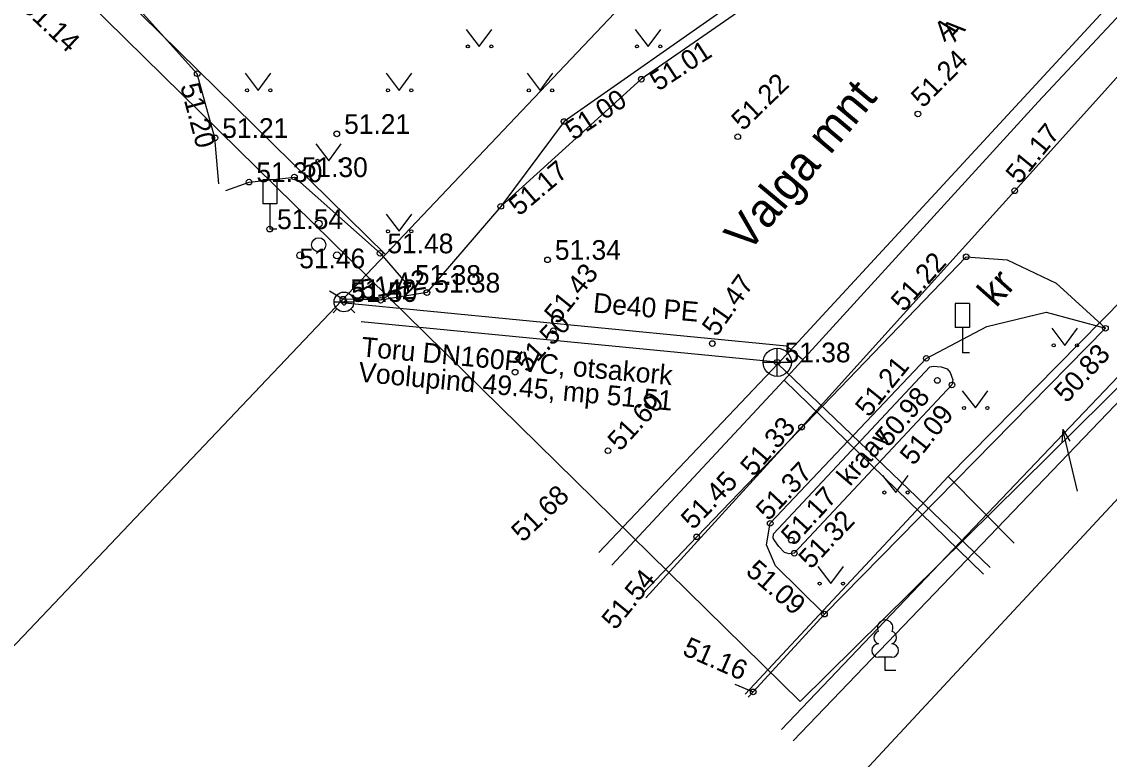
# Model space of a CAD drawing. Extents: x 640876 to 641418, y 6455595 to 6456085.
# Drawn here: x 641203.77 to 641242.36, y 6455734.7 to 6455760.88 of the extents above; entities that cross this region are included whole.
import ezdxf

# ---------------------------------------------------------------- set-up
doc = ezdxf.new("R2010")
doc.units = 0
for name, color, linetype in [('HALJASTUS', 7, 'Continuous'), ('KKAEV', 7, 'Continuous'), ('KORGUS', 7, 'Continuous'), ('KTRASS', 7, 'Continuous'), ('LIIKLUS', 7, 'Continuous'), ('MOOTKORG', 7, 'Continuous'), ('MOOTMPUNKT', 7, 'Continuous'), ('MOOTPIIR', 7, 'Continuous'), ('MPOHULIIN', 7, 'Continuous'), ('PIIR', 7, 'Continuous'), ('PUU', 7, 'Continuous'), ('SITRASS', 7, 'Continuous'), ('TEE', 7, 'Continuous'), ('VEEKOGU', 7, 'Continuous'), ('VKAEV', 7, 'Continuous'), ('VTRASS', 7, 'Continuous')]:
    doc.layers.add(name, color=color, linetype=linetype)

msp = doc.modelspace()

# ---------------------------------------------------------------- linework, layer by layer
at = {"layer": 'HALJASTUS'}
for p, q in [((641219.537, 6455760.607), (641220, 6455760)), ((641220, 6455760), (641220.446, 6455760.607)), ((641225.537, 6455760.607), (641226, 6455760)), ((641226, 6455760), (641226.446, 6455760.607)), ((641211.699, 6455759.047), (641212.162, 6455758.44)), ((641212.162, 6455758.44), (641212.608, 6455759.047)), ((641216.699, 6455759.047), (641217.162, 6455758.44)), ((641217.162, 6455758.44), (641217.608, 6455759.047)), ((641221.699, 6455759.047), (641222.162, 6455758.44)), ((641222.162, 6455758.44), (641222.608, 6455759.047)), ((641214.199, 6455756.547), (641214.662, 6455755.94)), ((641214.662, 6455755.94), (641215.108, 6455756.547)), ((641216.699, 6455754.047), (641217.162, 6455753.44)), ((641217.162, 6455753.44), (641217.608, 6455754.047)), ((641240.324, 6455749.995), (641240.787, 6455749.389)), ((641240.787, 6455749.389), (641241.233, 6455749.995)), ((641237.144, 6455747.774), (641237.607, 6455747.167)), ((641237.607, 6455747.167), (641238.053, 6455747.774)), ((641234.316, 6455744.77), (641234.78, 6455744.164)), ((641234.78, 6455744.164), (641235.225, 6455744.77)), ((641232.019, 6455741.539), (641232.483, 6455740.933)), ((641232.483, 6455740.933), (641232.928, 6455741.539))]:
    msp.add_line(p, q, dxfattribs=at)
msp.add_lwpolyline([(641211.007, 6455754.889), (641211.832, 6455755.185), (641213.444, 6455755.363), (641216.482, 6455752.657), (641217.46, 6455751.537), (641216.502, 6455750.988)], dxfattribs=at)
for centre in [(641219.599, 6455760), (641220.428, 6455760), (641225.599, 6455760), (641226.428, 6455760), (641211.761, 6455758.44), (641212.59, 6455758.44), (641216.761, 6455758.44), (641217.59, 6455758.44), (641221.761, 6455758.44), (641222.59, 6455758.44), (641214.261, 6455755.94), (641215.09, 6455755.94), (641216.761, 6455753.44), (641217.59, 6455753.44), (641240.386, 6455749.389), (641241.215, 6455749.389), (641237.206, 6455747.167), (641238.035, 6455747.167), (641234.379, 6455744.164), (641235.208, 6455744.164), (641232.082, 6455740.933), (641232.911, 6455740.933)]:
    msp.add_circle(centre, 0.055, dxfattribs=at)
at = {"layer": 'KKAEV'}
for p, q in [((641230.577, 6455748.287), (641230.577, 6455749.287)), ((641230.077, 6455748.787), (641231.077, 6455748.787))]:
    msp.add_line(p, q, dxfattribs=at)
msp.add_circle((641230.577, 6455748.787), 0.5, dxfattribs=at)
at = {"layer": 'KORGUS'}
for centre in [(641209.995, 6455759.033), (641225.754, 6455758.837), (641223.014, 6455757.336), (641235.569, 6455757.604), (641214.947, 6455756.896), (641229.176, 6455756.796), (641239.003, 6455754.877), (641220.766, 6455754.323), (641216.482, 6455752.657), (641237.282, 6455752.533), (641216.502, 6455750.988), (641242.224, 6455749.994), (641222.63, 6455749.907), (641228.271, 6455749.453), (641235.865, 6455748.928), (641221.275, 6455748.434), (641236.26, 6455748.144), (641236.777, 6455747.982), (641231.439, 6455746.488), (641224.569, 6455745.648), (641230.327, 6455743.071), (641227.72, 6455742.592), (641231.078, 6455742.473), (641231.181, 6455742.011), (641232.253, 6455739.847), (641229.724, 6455737.087)]:
    msp.add_circle(centre, 0.1, dxfattribs=at)
at = {"layer": 'KTRASS'}
msp.add_line((641230.577, 6455748.787), (641215.813, 6455750.225), dxfattribs=at)
for points in [[(641230.602, 6455748.736), (641246.182, 6455765.632)], [(641224.25, 6455742.039), (641230.602, 6455748.736), (641238.136, 6455741.504)]]:
    msp.add_lwpolyline(points, dxfattribs=at)
at = {"layer": 'LIIKLUS'}
for p, q in [((641212.318, 6455755.267), (641212.318, 6455754.417)), ((641212.818, 6455755.267), (641212.318, 6455755.267)), ((641212.818, 6455755.267), (641212.818, 6455754.417)), ((641212.818, 6455754.417), (641212.318, 6455754.417)), ((641212.568, 6455754.417), (641212.568, 6455753.517)), ((641212.818, 6455753.517), (641212.568, 6455753.517)), ((641236.896, 6455750.876), (641236.896, 6455750.026)), ((641237.396, 6455750.876), (641236.896, 6455750.876)), ((641237.396, 6455750.876), (641237.396, 6455750.026)), ((641237.396, 6455750.026), (641236.896, 6455750.026)), ((641237.146, 6455750.026), (641237.146, 6455749.126)), ((641237.396, 6455749.126), (641237.146, 6455749.126))]:
    msp.add_line(p, q, dxfattribs=at)
at = {"layer": 'MOOTMPUNKT'}
msp.add_line((641215.102, 6455750.915), (641215.188, 6455750.832), dxfattribs=at)
for centre in [(641210.623, 6455756.753), (641211.832, 6455755.185), (641213.444, 6455755.363), (641212.568, 6455753.517), (641222.426, 6455752.425), (641217.46, 6455751.537), (641218.145, 6455751.263), (641215.165, 6455751.027), (641230.577, 6455748.787)]:
    msp.add_circle(centre, 0.1, dxfattribs=at)
msp.add_arc((641215.201, 6455750.931), 0.1, 262.271, 189.4555, dxfattribs=at)
at = {"layer": 'MOOTPIIR'}
msp.add_lwpolyline([(641060.916, 6455895.936), (641100.061, 6455950.482), (641099.586, 6455952.159), (641069.132, 6455984.035), (641066.132, 6455988.623), (641076.463, 6456005.049), (641230.642, 6456010.048), (641237.36, 6455995.24), (641237.24, 6455992.81), (641236.258, 6455990.888), (641229.041, 6455971.315), (641203.026, 6455909.57), (641225.257, 6455906.847), (641239.512, 6455898.491), (641200.195, 6455851.697), (641192.016, 6455859.099), (641169.785, 6455829.138), (641192.025, 6455807.568), (641252.96, 6455758.075), (641231.388, 6455736.74), (641191.474, 6455775.975), (641152.419, 6455787.914), (641136.351, 6455788.307), (641049.066, 6455856.043)], dxfattribs=at)
at = {"layer": 'MPOHULIIN'}
for p, q in [((641240.716, 6455746.398), (641240.672, 6455745.924)), ((641240.716, 6455746.398), (641240.963, 6455745.992)), ((641241.227, 6455744.207), (641240.716, 6455746.398)), ((641241.284, 6455743.963), (641241.284, 6455743.963))]:
    msp.add_line(p, q, dxfattribs=at)
at = {"layer": 'PIIR'}
for points in [[(641216.67, 6455752.61), (641192, 6455776.86), (641152.58, 6455788.91), (641136.9, 6455789.33), (641119.28, 6455802.72), (641101.72, 6455816.27), (641098.61, 6455818.83), (641124.03, 6455849.78), (641139.51, 6455868.99), (641157, 6455885.69), (641191.84, 6455860.59), (641168.46, 6455829.03), (641191.37, 6455806.79), (641234.69, 6455771.62)], [(641216.67, 6455752.61), (641182.28, 6455716.38), (641177.47, 6455716.39), (641127.83, 6455755.09), (641138.89, 6455768.28), (641129.48, 6455779.82), (641136.9, 6455789.33), (641152.58, 6455788.91), (641192, 6455776.86)], [(641244.26, 6455745.67), (641262.56, 6455725.76), (641276.8, 6455710.41), (641291.83, 6455694.21), (641284.13, 6455685.93), (641271.03, 6455672.05), (641222.48, 6455722.23)]]:
    msp.add_lwpolyline(points, close=True, dxfattribs=at)
msp.add_lwpolyline([(641274.59, 6455777.38), (641265.59, 6455768.59), (641244.26, 6455745.67), (641222.48, 6455722.23), (641201.2, 6455700.54), (641180.13, 6455678.32), (641171.14, 6455668.19), (641142.12, 6455638.98), (641132.03, 6455627.4), (641101.1, 6455594.76), (641087.79, 6455611.35), (641100.72, 6455625.11), (641099.2, 6455626.54), (641113.86, 6455642.06), (641121.21, 6455649.84), (641140.58, 6455669.91), (641170.91, 6455704.35), (641182.28, 6455716.38), (641216.67, 6455752.61), (641234.69, 6455771.62), (641250.06, 6455787.79)], dxfattribs=at)
at = {"layer": 'PUU'}
for p, q in [((641234.647, 6455738.318), (641234.167, 6455738.318)), ((641234.407, 6455737.843), (641234.407, 6455738.318)), ((641234.787, 6455737.843), (641234.407, 6455737.843))]:
    msp.add_line(p, q, dxfattribs=at)
for centre, radius in [((641214.305, 6455753.708), 0.125), ((641214.305, 6455752.958), 0.25), ((641213.655, 6455752.583), 0.125), ((641214.955, 6455752.583), 0.125)]:
    msp.add_circle(centre, radius, dxfattribs=at)
for centre, radius, start, end in [((641234.407, 6455739.363), 0.277, 332.5799, 207.4201), ((641234.237, 6455739.016), 0.233, 109.0217, 253.1415), ((641234.577, 6455739.016), 0.233, 286.8508, 70.9859), ((641234.17, 6455738.555), 0.238, 90.0016, 269.3953), ((641234.644, 6455738.555), 0.238, 270.6047, 89.9984)]:
    msp.add_arc(centre, radius, start, end, dxfattribs=at)
at = {"layer": 'SITRASS'}
for points in [[(641236.642, 6455744.737), (641252.219, 6455760.55)], [(641230.725, 6455735.756), (641253.415, 6455759.543)], [(641229.441, 6455737.002), (641236.642, 6455744.737), (641238.99, 6455742.368)]]:
    msp.add_lwpolyline(points, dxfattribs=at)
at = {"layer": 'TEE'}
for points in [[(641210.623, 6455756.753), (641209.995, 6455759.033), (641206.274, 6455763.164), (641201.573, 6455767.409), (641194.555, 6455773.807), (641189.469, 6455777.839), (641187.027, 6455774.627)], [(641241.177, 6455769.846), (641238.101, 6455766.631), (641235.127, 6455765.375), (641229.134, 6455761.617), (641223.014, 6455757.336)], [(641238.93, 6455767.644), (641236.996, 6455765.75), (641234.974, 6455764.956), (641232.281, 6455763.369), (641225.754, 6455758.837), (641220.766, 6455754.323), (641218.145, 6455751.263), (641216.502, 6455750.988), (641215.165, 6455751.027), (641214.689, 6455751.315)], [(641245.685, 6455762.32), (641239.003, 6455754.877), (641231.439, 6455746.488), (641225.914, 6455740.424)], [(641223.014, 6455757.336), (641220.766, 6455754.323), (641218.145, 6455751.263), (641216.502, 6455750.988), (641215.165, 6455751.027), (641214.689, 6455751.315)], [(641210.761, 6455755.127), (641210.623, 6455756.753)], [(641225.782, 6455740.552), (641227.72, 6455742.592), (641237.282, 6455752.533), (641238.731, 6455752.429), (641240.469, 6455751.597), (641242.224, 6455749.994), (641232.253, 6455739.847), (641229.724, 6455737.087), (641229.548, 6455736.898)], [(641232.253, 6455739.847), (641230.513, 6455741.563), (641230.196, 6455742.306), (641230.327, 6455743.071), (641235.865, 6455748.928), (641238.015, 6455750.056), (641240.117, 6455750.569), (641242.224, 6455749.994)], [(641231.14, 6455735.353), (641244.518, 6455749.299)], [(641229.074, 6455737.358), (641229.724, 6455737.087)]]:
    msp.add_lwpolyline(points, dxfattribs=at)
at = {"layer": 'VEEKOGU'}
msp.add_lwpolyline([(641231.181, 6455742.011), (641230.996, 6455741.993), (641230.832, 6455742.038), (641230.63, 6455742.244), (641230.488, 6455742.448), (641230.437, 6455742.549), (641230.446, 6455742.693), (641235.992, 6455748.625), (641236.133, 6455748.652), (641236.251, 6455748.638), (641236.391, 6455748.621), (641236.611, 6455748.561), (641236.717, 6455748.429), (641236.76, 6455748.295), (641236.802, 6455748.17), (641236.777, 6455747.982), (641231.181, 6455742.011)], dxfattribs=at)
at = {"layer": 'VKAEV'}
for p, q in [((641214.851, 6455750.931), (641215.551, 6455750.931)), ((641214.954, 6455750.684), (641214.814, 6455750.544)), ((641215.448, 6455750.684), (641215.588, 6455750.544))]:
    msp.add_line(p, q, dxfattribs=at)
msp.add_circle((641215.201, 6455750.931), 0.35, dxfattribs=at)
at = {"layer": 'VTRASS'}
for points in [[(641230.82, 6455748.15), (641239.836, 6455758.035), (641246.602, 6455765.279)], [(641231.48, 6455748.88), (641230.9, 6455749.36), (641215.118, 6455750.899)], [(641224.711, 6455741.591), (641230.82, 6455748.15), (641237.897, 6455741.263)]]:
    msp.add_lwpolyline(points, dxfattribs=at)

# ---------------------------------------------------------------- texts
at = {"layer": 'KORGUS'}
for s, rotation, p in [(' 51.14', 316.5071, (641203.525, 6455761.534)), (' 51.01', 33.1043, (641226.136, 6455758.251)), (' 51.24', 45.3645, (641235.569, 6455757.604)), (' 51.22', 44.1153, (641229.176, 6455756.796)), (' 51.20', 284.8761, (641209.318, 6455758.853)), (' 51.00', 33.5709, (641223.132, 6455756.504)), (' 51.17', 50.8264, (641239.003, 6455754.877)), (' 51.17', 40.1719, (641221.218, 6455753.788)), (' 51.22', 48.434, (641234.894, 6455750.354)), (' 51.42', 9.5769, (641215.589, 6455750.968)), (' 51.43', 51.1515, (641222.63, 6455749.907)), (' 51.47', 54.5045, (641228.271, 6455749.453)), (' 51.50', 47.2838, (641221.532, 6455748.197)), (' 50.83', 47.4115, (641240.674, 6455747.12)), (' 51.21', 51.0234, (641233.663, 6455746.605)), (' 50.98', 49.8685, (641234.355, 6455745.545)), (' 51.60', 47.3313, (641224.826, 6455745.411)), (' 51.09', 51.5307, (641235.255, 6455744.889)), (' 51.33', 49.1554, (641229.563, 6455744.497)), (' 51.37', 46.7192, (641230.083, 6455742.938)), (' 51.45', 46.1133, (641227.413, 6455742.626)), (' 51.68', 43.6444, (641221.361, 6455742.19)), (' 51.17', 47.4482, (641230.984, 6455742.047)), (' 51.32', 46.7565, (641231.593, 6455741.225)), (' 51.09', 319.0856, (641229.226, 6455741.478)), (' 51.54', 50.8436, (641224.663, 6455739.052)), (' 51.16', 336.3595, (641226.934, 6455738.524))]:
    msp.add_text(s, height=0.7, rotation=rotation, dxfattribs=at).set_placement(p)
for s, p in [(' 51.21', (641214.947, 6455756.896)), (' 51.48', (641216.482, 6455752.657))]:
    msp.add_text(s, height=0.7, dxfattribs=at).set_placement(p)
at = {"layer": 'KTRASS'}
for s, p in [('Toru DN160PVC, otsakork', (641215.791, 6455748.997)), ('Voolupind 49.45, mp 51.51', (641215.691, 6455748.103))]:
    msp.add_text(s, height=0.7, rotation=354.7023, dxfattribs=at).set_placement(p)
at = {"layer": 'MOOTKORG'}
for s, p in [(' 51.21', (641210.623, 6455756.753)), (' 51.30', (641211.832, 6455755.185)), (' 51.30', (641213.444, 6455755.363)), (' 51.54', (641212.568, 6455753.517)), (' 51.46', (641213.354, 6455752.125)), (' 51.34', (641222.426, 6455752.425)), (' 51.38', (641217.46, 6455751.537)), (' 51.42', (641215.165, 6455751.027)), (' 51.50', (641215.201, 6455750.931)), (' 51.38', (641218.145, 6455751.263)), (' 51.38', (641230.577, 6455748.787))]:
    msp.add_text(s, height=0.7, dxfattribs=at).set_placement(p)
at = {"layer": 'TEE'}
for s, height, rotation, p in [('A', 0.7, 39.0355, (641236.505, 6455760.148)), ('A', 0.7, 48.3825, (641236.878, 6455760.137)), ('Valga mnt', 1.2, 50.1084, (641229.532, 6455752.632)), ('kr', 1, 48.3665, (641238.345, 6455750.697))]:
    msp.add_text(s, height=height, rotation=rotation, dxfattribs=at).set_placement(p)
at = {"layer": 'VEEKOGU'}
msp.add_text('kraav', height=0.7, rotation=49.6045, dxfattribs=at).set_placement((641233.159, 6455744.357))
at = {"layer": 'VTRASS'}
msp.add_text('De40 PE', height=0.7, rotation=354.895, dxfattribs=at).set_placement((641224.023, 6455750.56))

doc.saveas('drawing.dxf')
